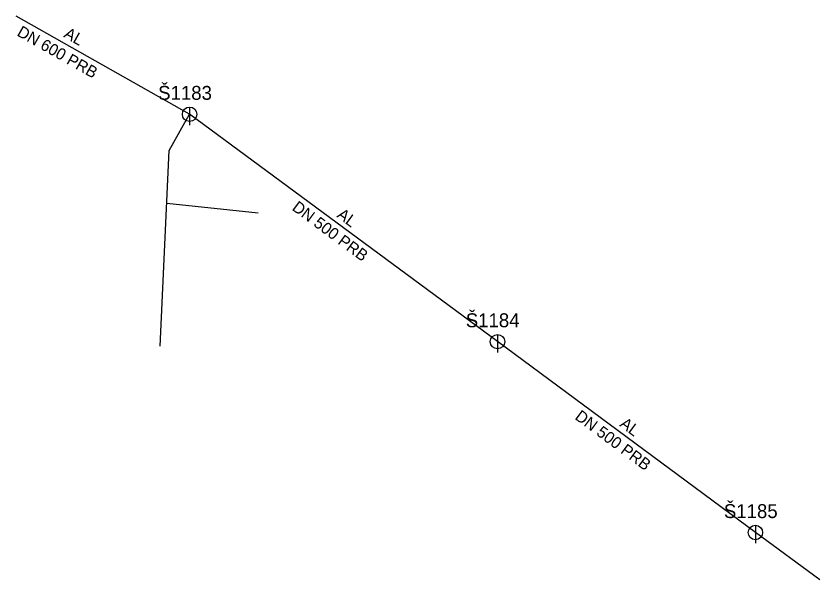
# Model space of a CAD drawing. Extents: x -482807 to -482696, y -1127528 to -1127450.
import ezdxf

# ---------------------------------------------------------------- set-up
doc = ezdxf.new("R2010")
doc.units = 0
for name, color, linetype in [('_pripojka_kanal_destova_priblizne_', 7, 'Continuous'), ('_stoka_jednotna_smvak_prevzato_z_dokumentace_', 7, 'Continuous'), ('Default', 7, 'Continuous'), ('MoLevel 119', 7, 'Continuous'), ('MoLevel 120', 7, 'Continuous'), ('MoLevel 68', 7, 'Continuous'), ('MoLevel 69', 7, 'Continuous')]:
    doc.layers.add(name, color=color, linetype=linetype)

# ---------------------------------------------------------------- blocks, each defined once
blk = doc.blocks.new('_sachta_kanal_prevzato_z_dokumentace_')
at = {"layer": 'Default'}
blk.add_line((0, 0.00005), (0, -0.000075), dxfattribs=at)
blk.add_circle((0, 0), 0.00005, dxfattribs=at)

msp = doc.modelspace()

# ---------------------------------------------------------------- linework, layer by layer
at = {"layer": '_pripojka_kanal_destova_priblizne_'}
msp.add_line((-482773.71, -1127477.52), (-482786.38, -1127476.2), dxfattribs=at)
msp.add_lwpolyline([(-482787.29, -1127495.94), (-482786.04, -1127468.85), (-482783.21, -1127463.81)], dxfattribs=at)
at = {"layer": '_stoka_jednotna_smvak_prevzato_z_dokumentace_'}
for p, q in [((-482783.21, -1127463.81), (-482807.25, -1127450.2)), ((-482740.57, -1127495.33), (-482783.21, -1127463.81)), ((-482704.86, -1127521.78), (-482740.57, -1127495.33)), ((-482695.92, -1127528.35), (-482704.86, -1127521.78))]:
    msp.add_line(p, q, dxfattribs=at)

# ---------------------------------------------------------------- block references
at = {"layer": 'MoLevel 119', "xscale": 20000, "yscale": 20000}
for p in [(-482783.21, -1127463.81), (-482740.57, -1127495.33), (-482704.86, -1127521.78)]:
    msp.add_blockref('_sachta_kanal_prevzato_z_dokumentace_', p, dxfattribs=at)

# ---------------------------------------------------------------- texts
at = {"layer": 'MoLevel 120'}
for s, p in [('Š1183', (-482787.57, -1127461.81)), ('Š1184', (-482744.97, -1127493.33)), ('Š1185', (-482709.22, -1127519.78))]:
    msp.add_text(s, height=1.926, dxfattribs=at).set_placement(p)
at = {"layer": 'MoLevel 68'}
for s, rotation, p in [('DN 600 PRB', 330.4831, (-482807.24, -1127452.85)), ('DN 500 PRB', 323.5277, (-482769.14, -1127477)), ('DN 500 PRB', 323.4731, (-482729.97, -1127505.98))]:
    msp.add_text(s, height=1.605, rotation=rotation, dxfattribs=at).set_placement(p)
at = {"layer": 'MoLevel 69'}
for rotation, p in [(330.4831, (-482800.76, -1127453.07)), (323.5277, (-482762.93, -1127478)), (323.4731, (-482723.76, -1127506.98))]:
    msp.add_text('AL', height=1.605, rotation=rotation, dxfattribs=at).set_placement(p)

doc.saveas('drawing.dxf')
